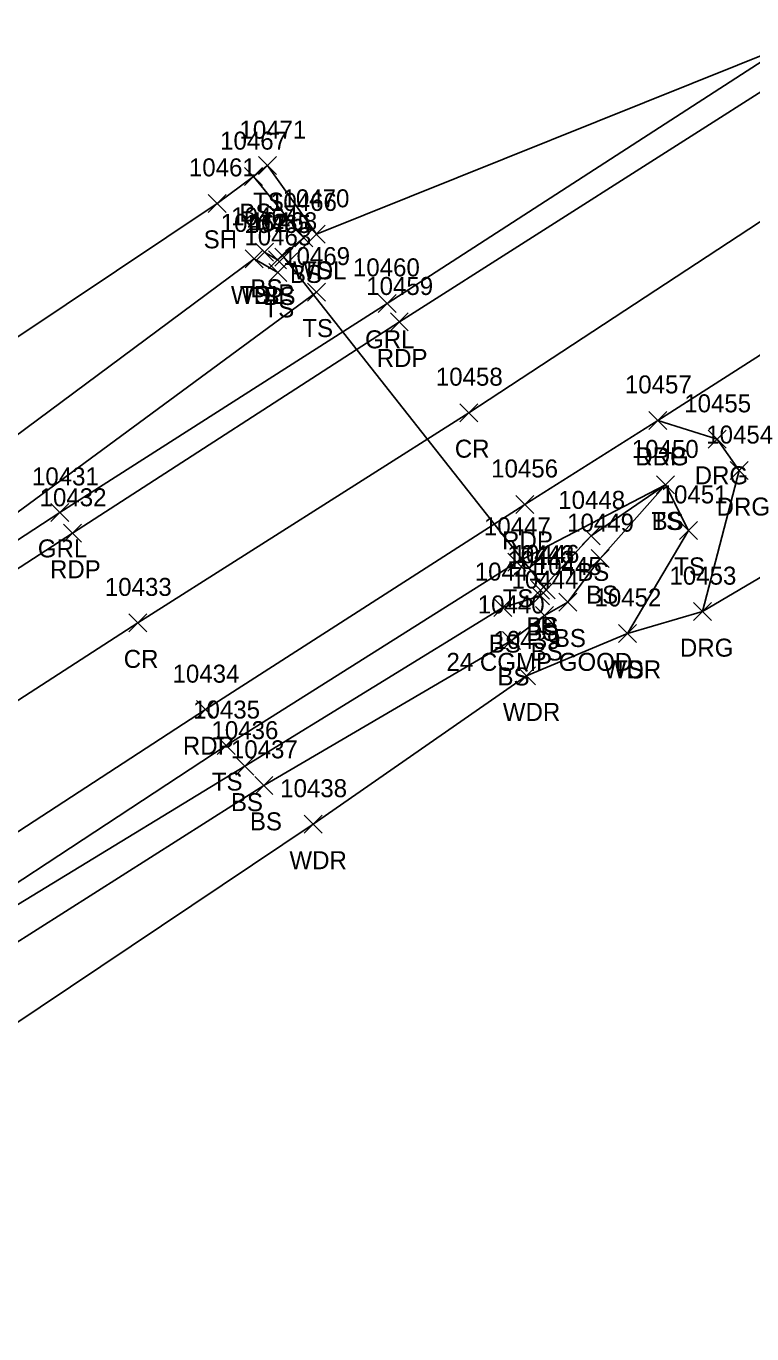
# Model space of a CAD drawing. Extents: x 1651685 to 1653558, y 889533 to 891085.
# Drawn here: x 1653107 to 1653187.7, y 890725 to 890870.3 of the extents above; entities that cross this region are included whole.
import ezdxf

# ---------------------------------------------------------------- set-up
doc = ezdxf.new("R2010")
doc.units = 0
for name, color, linetype in [('D_A', 7, 'Continuous'), ('D_C', 7, 'Continuous'), ('D_I', 7, 'Continuous'), ('D_TIC', 7, 'Continuous'), ('DCP', 7, 'Continuous'), ('L_A', 7, 'Continuous'), ('L_I', 7, 'Continuous'), ('L_TIC', 7, 'Continuous'), ('LAWA', 7, 'Continuous'), ('LELB', 7, 'Continuous'), ('LSOGP', 7, 'Continuous'), ('P_A', 7, 'Continuous'), ('P_I', 7, 'Continuous'), ('P_TIC', 7, 'Continuous'), ('PET', 7, 'Continuous'), ('PRC', 7, 'Continuous'), ('R_A', 7, 'Continuous'), ('R_I', 7, 'Continuous'), ('R_TIC', 7, 'Continuous'), ('RDG', 7, 'Continuous'), ('RGR', 7, 'Continuous')]:
    doc.layers.add(name, color=color, linetype=linetype)

msp = doc.modelspace()

# ---------------------------------------------------------------- linework, layer by layer
at = {"layer": 'D_TIC'}
for points in [[(1653134.63, 890843.66), (1653136.63, 890845.66)], [(1653136.63, 890843.66), (1653134.63, 890845.66)], [(1653163.79, 890806.7), (1653165.79, 890808.7)], [(1653165.79, 890806.7), (1653163.79, 890808.7)]]:
    msp.add_lwpolyline(points, dxfattribs=at)
at = {"layer": 'DCP'}
msp.add_lwpolyline([(1653164.79, 890807.7), (1653135.63, 890844.66)], dxfattribs=at)
at = {"layer": 'L_TIC'}
for points in [[(1653132.81, 890853.84), (1653134.81, 890855.84)], [(1653134.81, 890853.84), (1653132.81, 890855.84)], [(1653131.26, 890852.62), (1653133.26, 890854.62)], [(1653133.26, 890852.62), (1653131.26, 890854.62)], [(1653127.23, 890849.65), (1653129.23, 890851.65)], [(1653129.23, 890849.65), (1653127.23, 890851.65)], [(1653136.87, 890845.81), (1653138.87, 890847.81)], [(1653138.87, 890845.81), (1653136.87, 890847.81)], [(1653138.25, 890846.21), (1653140.25, 890848.21)], [(1653140.25, 890846.21), (1653138.25, 890848.21)], [(1653138.25, 890846.21), (1653140.25, 890848.21)], [(1653140.25, 890846.21), (1653138.25, 890848.21)], [(1653132.49, 890844.21), (1653134.49, 890846.21)], [(1653134.49, 890844.21), (1653132.49, 890846.21)], [(1653131.33, 890843.48), (1653133.33, 890845.48)], [(1653133.33, 890843.48), (1653131.33, 890845.48)], [(1653131.33, 890843.48), (1653133.33, 890845.48)], [(1653133.33, 890843.48), (1653131.33, 890845.48)], [(1653133.92, 890843.36), (1653135.92, 890845.36)], [(1653135.92, 890843.36), (1653133.92, 890845.36)], [(1653133.97, 890841.98), (1653135.97, 890843.98)], [(1653135.97, 890841.98), (1653133.97, 890843.98)], [(1653138.28, 890839.79), (1653140.28, 890841.79)], [(1653140.28, 890839.79), (1653138.28, 890841.79)], [(1653177.09, 890818.36), (1653179.09, 890820.36)], [(1653179.09, 890818.36), (1653177.09, 890820.36)], [(1653177.09, 890818.36), (1653179.09, 890820.36)], [(1653179.09, 890818.36), (1653177.09, 890820.36)], [(1653177.09, 890818.36), (1653179.09, 890820.36)], [(1653179.09, 890818.36), (1653177.09, 890820.36)], [(1653168.82, 890812.7), (1653170.82, 890814.7)], [(1653170.82, 890812.7), (1653168.82, 890814.7)], [(1653179.64, 890813.31), (1653181.64, 890815.31)], [(1653181.64, 890813.31), (1653179.64, 890815.31)], [(1653160.56, 890809.77), (1653162.56, 890811.77)], [(1653162.56, 890809.77), (1653160.56, 890811.77)], [(1653169.81, 890810.17), (1653171.81, 890812.17)], [(1653171.81, 890810.17), (1653169.81, 890812.17)], [(1653163.17, 890806.66), (1653165.17, 890808.66)], [(1653165.17, 890806.66), (1653163.17, 890808.66)], [(1653163.16, 890806.03), (1653165.16, 890808.03)], [(1653165.16, 890806.03), (1653163.16, 890808.03)], [(1653166.22, 890805.35), (1653168.22, 890807.35)], [(1653168.22, 890805.35), (1653166.22, 890807.35)], [(1653158.98, 890804.73), (1653160.98, 890806.73)], [(1653160.98, 890804.73), (1653158.98, 890806.73)], [(1653163.63, 890803.85), (1653165.63, 890805.85)], [(1653165.63, 890803.85), (1653163.63, 890805.85)], [(1653172.84, 890801.86), (1653174.84, 890803.86)], [(1653174.84, 890801.86), (1653172.84, 890803.86)], [(1653172.84, 890801.86), (1653174.84, 890803.86)], [(1653174.84, 890801.86), (1653172.84, 890803.86)], [(1653159.95, 890801.08), (1653161.95, 890803.08)], [(1653161.95, 890801.08), (1653159.95, 890803.08)], [(1653161.63, 890797.14), (1653163.63, 890799.14)], [(1653163.63, 890797.14), (1653161.63, 890799.14)], [(1653128.22, 890789.4), (1653130.22, 890791.4)], [(1653130.22, 890789.4), (1653128.22, 890791.4)], [(1653130.31, 890787.11), (1653132.31, 890789.11)], [(1653132.31, 890787.11), (1653130.31, 890789.11)], [(1653132.42, 890784.98), (1653134.42, 890786.98)], [(1653134.42, 890784.98), (1653132.42, 890786.98)], [(1653137.9, 890780.66), (1653139.9, 890782.66)], [(1653139.9, 890780.66), (1653137.9, 890782.66)]]:
    msp.add_lwpolyline(points, dxfattribs=at)
at = {"layer": 'LAWA'}
for points in [[(1652817.98, 890613.54), (1652840.14, 890627.46), (1652861.15, 890647.29), (1652878.51, 890666.18), (1652884.26, 890671.52), (1652922.69, 890701.4), (1652959.19, 890728.02), (1652986.15, 890746.08), (1653025.9, 890769.89), (1653049.43, 890788.17), (1653075.47, 890803.38), (1653097.52, 890818.66), (1653132.33, 890844.48)], [(1652833.35, 890477.68), (1652833.39, 890492.3), (1652850.18, 890532.6), (1652867.73, 890564.2), (1652876.6, 890576.01), (1652892.95, 890598.85), (1652902.11, 890607.6), (1652908.8, 890618.44), (1652924.22, 890630.58), (1652962.12, 890654.07), (1652988.27, 890674.02), (1653019.66, 890699.72), (1653055.48, 890726.92), (1653095, 890752.3), (1653138.9, 890781.66), (1653162.63, 890798.14), (1653173.84, 890802.86)]]:
    msp.add_lwpolyline(points, dxfattribs=at)
at = {"layer": 'LELB'}
for points in [[(1653132.33, 890844.48), (1653134.97, 890842.98), (1653139.25, 890847.21), (1653133.81, 890854.84)], [(1653133.49, 890845.21), (1653134.92, 890844.36), (1653137.87, 890846.81), (1653132.26, 890853.62)], [(1652773.03, 890464.56), (1652787.9, 890509.35), (1652802.92, 890548.75), (1652814.17, 890571.87), (1652832.16, 890602.17), (1652848.73, 890624.66), (1652866.01, 890644.23), (1652889.12, 890668.57), (1652926.33, 890696.32), (1652964.24, 890723.35), (1652991.22, 890740.2), (1653028.13, 890766.86), (1653057.75, 890784.91), (1653079.01, 890799.53), (1653102.53, 890813.78), (1653139.28, 890840.79)], [(1652801.17, 890441.9), (1652819.95, 890497.78), (1652834.5, 890541.46), (1652846.59, 890562.12), (1652860.39, 890582.03), (1652876.07, 890602.68), (1652893.78, 890623.65), (1652912.56, 890642.08), (1652928.52, 890655.01), (1652947.04, 890668.65), (1652977.97, 890691.06), (1653009.95, 890711.96), (1653047.06, 890737.13), (1653086.67, 890762.46), (1653129.22, 890790.4), (1653161.56, 890810.77), (1653178.09, 890819.36), (1653180.64, 890814.31), (1653173.84, 890802.86)], [(1652803.19, 890441), (1652820.95, 890497.33), (1652835.58, 890541.15), (1652847.79, 890560.97), (1652861.63, 890580.86), (1652877.83, 890601.57), (1652890.21, 890617.22), (1652895.56, 890622.27), (1652897.12, 890622.95), (1652897.22, 890624.03), (1652915.57, 890639.3), (1652930.05, 890653.23), (1652948.11, 890667.03), (1652978.83, 890689.41), (1653011.67, 890709.88), (1653048.76, 890734.73), (1653087.02, 890761.14), (1653131.31, 890788.11), (1653159.98, 890805.73), (1653164.16, 890807.03), (1653164.17, 890807.66), (1653169.82, 890813.7), (1653178.09, 890819.36)], [(1652803.19, 890441), (1652822.35, 890480.19), (1652822.96, 890495.87), (1652838.19, 890539.83), (1652849.62, 890560.27), (1652863.19, 890579.04), (1652878.87, 890600.11), (1652891.82, 890615.8), (1652896.5, 890621.01), (1652897.47, 890622.7), (1652898.8, 890623.23), (1652915.57, 890639.3), (1652950.1, 890665.22), (1652980.52, 890686.66), (1653013.67, 890707.26), (1653050.87, 890733.01), (1653089.27, 890757.95), (1653133.42, 890785.98), (1653160.95, 890802.08), (1653164.63, 890804.85), (1653167.22, 890806.35), (1653170.81, 890811.17), (1653178.09, 890819.36)]]:
    msp.add_lwpolyline(points, dxfattribs=at)
at = {"layer": 'LSOGP'}
for points in [[(1653191.35, 890868.11), (1653139.25, 890847.21), (1653133.81, 890854.84), (1653132.26, 890853.62), (1653128.23, 890850.65), (1653088.88, 890824.36), (1653067.93, 890808.39), (1653036.42, 890796.38), (1653023.39, 890789.29), (1652975.72, 890758.11), (1652938.51, 890752.73), (1652900.6, 890736.09), (1652902.13, 890723.86), (1652868.79, 890705.34), (1652839.11, 890687.76), (1652822.21, 890657.08), (1652787.43, 890617.81), (1652783.5, 890592.65), (1652777.63, 890568.95), (1652768.73, 890549.07), (1652760.18, 890544.48), (1652755.23, 890514.52), (1652738.16, 890487.37)], [(1652860.84, 890470.43), (1652866.91, 890496.63), (1652876.03, 890531.03), (1652888.38, 890556.27), (1652912.99, 890585.04), (1652934.21, 890597.75), (1652965.72, 890622.73), (1652993.55, 890638.61), (1652995.94, 890655.58), (1652988.27, 890674.02), (1653019.66, 890699.72), (1653059.51, 890723.89), (1653095, 890752.3), (1653138.9, 890781.66), (1653162.63, 890798.14), (1653173.85, 890802.86), (1653182.19, 890805.28), (1653198.8, 890815.08)]]:
    msp.add_lwpolyline(points, dxfattribs=at)
at = {"layer": 'P_TIC'}
for points in [[(1653147.48, 890836.47), (1653149.48, 890838.47)], [(1653149.48, 890836.47), (1653147.48, 890838.47)], [(1653155.21, 890826.39), (1653157.21, 890828.39)], [(1653157.21, 890826.39), (1653155.21, 890828.39)], [(1653176.23, 890825.53), (1653178.23, 890827.53)], [(1653178.23, 890825.53), (1653176.23, 890827.53)], [(1653161.42, 890816.19), (1653163.42, 890818.19)], [(1653163.42, 890816.19), (1653161.42, 890818.19)], [(1653111.15, 890812.99), (1653113.15, 890814.99)], [(1653113.15, 890812.99), (1653111.15, 890814.99)], [(1653118.4, 890803.03), (1653120.4, 890805.03)], [(1653120.4, 890803.03), (1653118.4, 890805.03)], [(1653125.92, 890793.39), (1653127.92, 890795.39)], [(1653127.92, 890793.39), (1653125.92, 890795.39)]]:
    msp.add_lwpolyline(points, dxfattribs=at)
at = {"layer": 'PET'}
for points in [[(1652776.68, 890458.63), (1652791.9, 890507.53), (1652801.72, 890533.82), (1652810.09, 890553.36), (1652823.07, 890577.38), (1652836.65, 890598.71), (1652853.5, 890620.62), (1652874.5, 890644.55), (1652894.69, 890663.43), (1652909.83, 890677.02), (1652929.28, 890691.96), (1652967.44, 890717.98), (1652993.7, 890736.14), (1653032.31, 890761.89), (1653070.4, 890786.93), (1653112.15, 890813.99), (1653148.48, 890837.47), (1653192.87, 890865.71), (1653235.94, 890893.09), (1653280.18, 890921.16), (1653320.29, 890946.68)], [(1652797.7, 890444.76), (1652815.98, 890499.36), (1652826.44, 890526.94), (1652833.17, 890541.97), (1652844.38, 890563.93), (1652857.27, 890583.87), (1652872.84, 890604.95), (1652891.59, 890626.08), (1652910.84, 890643.86), (1652926.01, 890657.3), (1652944.49, 890672.05), (1652975.79, 890694.46), (1653007.52, 890715.91), (1653044.82, 890740.95), (1653083.79, 890766.34), (1653126.92, 890794.39), (1653162.42, 890817.19), (1653177.23, 890826.53), (1653212.82, 890849.27), (1653251.6, 890873.99), (1653294.22, 890900.69), (1653334.65, 890925.85)]]:
    msp.add_lwpolyline(points, dxfattribs=at)
at = {"layer": 'PRC'}
msp.add_lwpolyline([(1652786.21, 890448.94), (1652804.54, 890503.78), (1652815.08, 890532.72), (1652822.08, 890547.99), (1652834.04, 890571.05), (1652846.73, 890591.11), (1652862.72, 890612.73), (1652882.99, 890635.62), (1652902.76, 890654.37), (1652917.73, 890667.19), (1652936.47, 890681.71), (1652967.99, 890703.84), (1653000.43, 890726.04), (1653038.85, 890751.54), (1653077.14, 890776.73), (1653119.4, 890804.03), (1653156.21, 890827.39), (1653198.86, 890855.33), (1653243.54, 890883.44), (1653287.35, 890911.24), (1653327.74, 890936.2)], dxfattribs=at)
at = {"layer": 'R_TIC'}
for points in [[(1653146.12, 890838.54), (1653148.12, 890840.54)], [(1653148.12, 890838.54), (1653146.12, 890840.54)], [(1653176.23, 890825.53), (1653178.23, 890827.53)], [(1653178.23, 890825.53), (1653176.23, 890827.53)], [(1653182.83, 890823.43), (1653184.83, 890825.43)], [(1653184.83, 890823.43), (1653182.83, 890825.43)], [(1653185.28, 890819.96), (1653187.28, 890821.96)], [(1653187.28, 890819.96), (1653185.28, 890821.96)], [(1653109.73, 890815.31), (1653111.73, 890817.31)], [(1653111.73, 890815.31), (1653109.73, 890817.31)], [(1653181.19, 890804.28), (1653183.19, 890806.28)], [(1653183.19, 890804.28), (1653181.19, 890806.28)]]:
    msp.add_lwpolyline(points, dxfattribs=at)
at = {"layer": 'RDG'}
msp.add_lwpolyline([(1653182.19, 890805.28), (1653186.28, 890820.96), (1653183.83, 890824.43), (1653177.23, 890826.53)], dxfattribs=at)
at = {"layer": 'RGR'}
msp.add_lwpolyline([(1652753.62, 890407.5), (1652763.75, 890431.04), (1652774.48, 890459.79), (1652790.93, 890508.17), (1652800.51, 890534.29), (1652809.1, 890554.07), (1652821.88, 890578.18), (1652835.53, 890599.08), (1652852.44, 890621.25), (1652873.86, 890645.38), (1652894.3, 890664.88), (1652909.53, 890677.55), (1652928.71, 890692.69), (1652967.13, 890720.62), (1652991.99, 890738.03), (1653030.5, 890764.27), (1653069.01, 890789.08), (1653110.73, 890816.31), (1653147.12, 890839.54), (1653191.34, 890868.1), (1653234.07, 890895.44), (1653279.07, 890923.79), (1653318.83, 890948.74)], dxfattribs=at)

# ---------------------------------------------------------------- texts
at = {"layer": 'D_A'}
for p in [(1653135.01, 890839.66), (1653164.17, 890802.7)]:
    msp.add_text('P', height=2, dxfattribs=at).set_placement(p)
at = {"layer": 'D_C'}
msp.add_text('24 CGMP GOOD', height=2, dxfattribs=at).set_placement((1653153.72, 890798.7))
at = {"layer": 'D_I'}
for s, p in [('10468', (1653131.91, 890847.66)), ('10446', (1653161.06, 890810.7))]:
    msp.add_text(s, height=2, dxfattribs=at).set_placement(p)
at = {"layer": 'L_A'}
for s, p in [('TS', (1653132.22, 890849.84)), ('BS', (1653130.7, 890848.62)), ('SH', (1653126.72, 890845.65)), ('BS', (1653136.31, 890841.81)), ('WDL', (1653136.66, 890842.21)), ('TS', (1653137.66, 890842.21)), ('BS', (1653131.93, 890840.21)), ('WDL', (1653129.75, 890839.48)), ('TS', (1653130.74, 890839.48)), ('BS', (1653133.37, 890839.36)), ('TS', (1653133.38, 890837.98)), ('TS', (1653137.69, 890835.79)), ('TS', (1653176.5, 890814.36)), ('BS', (1653176.53, 890814.36)), ('BS', (1653176.53, 890814.36)), ('TS', (1653179.05, 890809.31)), ('BS', (1653168.26, 890808.7)), ('BS', (1653169.25, 890806.17)), ('TS', (1653159.97, 890805.77)), ('BS', (1653162.6, 890802.03)), ('BS', (1653162.61, 890802.66)), ('BS', (1653158.42, 890800.73)), ('BS', (1653165.66, 890801.35)), ('BS', (1653163.07, 890799.85)), ('WDR', (1653171.21, 890797.86)), ('TS', (1653172.25, 890797.86)), ('BS', (1653159.39, 890797.08)), ('WDR', (1653159.99, 890793.14)), ('TS', (1653127.63, 890785.4)), ('BS', (1653129.75, 890783.11)), ('BS', (1653131.86, 890780.98)), ('WDR', (1653136.26, 890776.66))]:
    msp.add_text(s, height=2, dxfattribs=at).set_placement(p)
at = {"layer": 'L_I'}
for s, p in [('10471', (1653130.7, 890857.84)), ('10467', (1653128.55, 890856.62)), ('10461', (1653125.08, 890853.65)), ('10466', (1653134.1, 890849.81)), ('10470', (1653135.49, 890850.21)), ('10470', (1653135.49, 890850.21)), ('10462', (1653128.62, 890847.48)), ('10462', (1653128.62, 890847.48)), ('10464', (1653129.78, 890848.21)), ('10465', (1653131.21, 890847.36)), ('10463', (1653131.25, 890845.98)), ('10469', (1653135.56, 890843.79)), ('10450', (1653174.33, 890822.36)), ('10450', (1653174.33, 890822.36)), ('10450', (1653174.33, 890822.36)), ('10448', (1653166.15, 890816.7)), ('10451', (1653177.54, 890817.31)), ('10447', (1653157.89, 890813.77)), ('10449', (1653167.14, 890814.17)), ('10443', (1653160.5, 890810.66)), ('10442', (1653160.49, 890810.03)), ('10445', (1653163.55, 890809.35)), ('10441', (1653156.87, 890808.73)), ('10444', (1653160.96, 890807.85)), ('10440', (1653157.2, 890805.08)), ('10452', (1653170.18, 890805.86)), ('10452', (1653170.18, 890805.86)), ('10439', (1653158.95, 890801.14)), ('10435', (1653125.55, 890793.4)), ('10436', (1653127.59, 890791.11)), ('10437', (1653129.75, 890788.98)), ('10438', (1653135.23, 890784.66))]:
    msp.add_text(s, height=2, dxfattribs=at).set_placement(p)
at = {"layer": 'P_A'}
for s, p in [('RDP', (1653145.97, 890832.47)), ('CR', (1653154.65, 890822.39)), ('RDP', (1653174.71, 890821.53)), ('RDP', (1653159.91, 890812.19)), ('RDP', (1653109.63, 890808.99)), ('CR', (1653117.83, 890799.03)), ('RDP', (1653124.41, 890789.39))]:
    msp.add_text(s, height=2, dxfattribs=at).set_placement(p)
at = {"layer": 'P_I'}
for s, p in [('10459', (1653144.8, 890840.47)), ('10458', (1653152.54, 890830.39)), ('10457', (1653173.56, 890829.53)), ('10456', (1653158.69, 890820.19)), ('10432', (1653108.48, 890816.99)), ('10433', (1653115.73, 890807.03)), ('10434', (1653123.26, 890797.39))]:
    msp.add_text(s, height=2, dxfattribs=at).set_placement(p)
at = {"layer": 'R_A'}
for s, p in [('GRL', (1653144.67, 890834.54)), ('DRG', (1653174.71, 890821.53)), ('DRG', (1653181.32, 890819.43)), ('DRG', (1653183.76, 890815.96)), ('GRL', (1653108.28, 890811.31)), ('DRG', (1653179.68, 890800.28))]:
    msp.add_text(s, height=2, dxfattribs=at).set_placement(p)
at = {"layer": 'R_I'}
for s, p in [('10460', (1653143.32, 890842.54)), ('10457', (1653173.56, 890829.53)), ('10455', (1653180.16, 890827.43)), ('10454', (1653182.61, 890823.96)), ('10431', (1653107.63, 890819.31)), ('10453', (1653178.52, 890808.28))]:
    msp.add_text(s, height=2, dxfattribs=at).set_placement(p)

doc.saveas('drawing.dxf')
